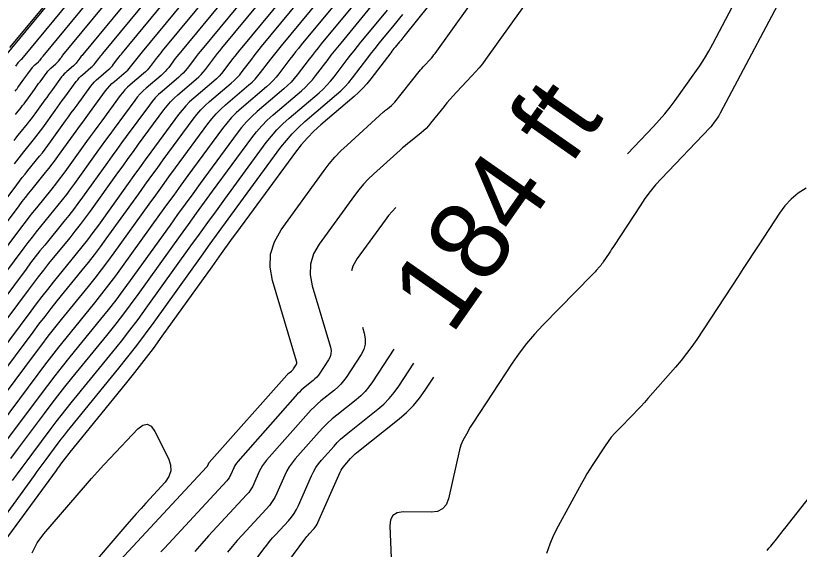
# Model space of a CAD drawing. Extents: x 7585033 to 7595090, y 547091 to 553471.
# Drawn here: x 7587044.7 to 7587106.7, y 548097.5 to 548139.7 of the extents above; entities that cross this region are included whole.
import ezdxf

# ---------------------------------------------------------------- set-up
doc = ezdxf.new("R2010")
doc.units = 0
for name, color, linetype in [('E_TERR_DSPLAY_GeneralTx', 7, 'Continuous'), ('E_TERR_DSPLAY_MajContour', 7, 'Continuous'), ('E_TERR_DSPLAY_MinContour', 7, 'Continuous')]:
    doc.layers.add(name, color=color, linetype=linetype)

msp = doc.modelspace()

# ---------------------------------------------------------------- linework, layer by layer
at = {"layer": 'E_TERR_DSPLAY_MajContour'}
for points in [[(7587067.906, 548163.768), (7587045.286, 548136.421), (7587045.27, 548136.402), (7587045.255, 548136.383), (7587045.24, 548136.363), (7587045.224, 548136.343), (7587045.164, 548136.264), (7587045.148, 548136.245), (7587045.132, 548136.226), (7587045.114, 548136.209), (7587045.096, 548136.192), (7587044.959, 548136.076), (7587044.931, 548136.05), (7587044.904, 548136.023), (7587044.879, 548135.995), (7587044.856, 548135.965), (7587044.668, 548135.708)], [(7587044.586, 548127.968), (7587044.768, 548128.209), (7587044.952, 548128.449), (7587045.139, 548128.686), (7587045.329, 548128.921), (7587046.093, 548129.858), (7587046.282, 548130.094), (7587046.467, 548130.333), (7587046.649, 548130.574), (7587046.827, 548130.818), (7587047.819, 548132.198), (7587048.005, 548132.457), (7587048.193, 548132.716), (7587048.381, 548132.974), (7587048.57, 548133.232), (7587049.485, 548134.478), (7587049.599, 548134.624), (7587049.721, 548134.763), (7587049.85, 548134.894), (7587049.988, 548135.018), (7587050.651, 548135.582), (7587050.741, 548135.663), (7587050.826, 548135.748), (7587050.906, 548135.837), (7587050.982, 548135.932), (7587051.275, 548136.317), (7587051.349, 548136.413), (7587051.424, 548136.508), (7587051.5, 548136.603), (7587051.576, 548136.696), (7587068.498, 548157.153)], [(7587069.089, 548150.539), (7587057.866, 548136.971), (7587057.729, 548136.803), (7587057.593, 548136.634), (7587057.459, 548136.463), (7587057.326, 548136.291), (7587056.8, 548135.599), (7587056.665, 548135.43), (7587056.52, 548135.27), (7587056.368, 548135.117), (7587056.206, 548134.972), (7587055.016, 548133.96), (7587054.769, 548133.738), (7587054.537, 548133.502), (7587054.319, 548133.254), (7587054.115, 548132.992), (7587052.472, 548130.755), (7587052.133, 548130.293), (7587051.796, 548129.829), (7587051.459, 548129.365), (7587051.124, 548128.9), (7587049.345, 548126.424), (7587049.026, 548125.986), (7587048.699, 548125.553), (7587048.367, 548125.125), (7587048.027, 548124.702), (7587046.657, 548123.021), (7587046.317, 548122.599), (7587045.981, 548122.173), (7587045.65, 548121.744), (7587045.324, 548121.311), (7587032.978, 548104.768)], [(7587038.984, 548105.17), (7587046.061, 548114.653), (7587046.532, 548115.278), (7587047.01, 548115.897), (7587047.495, 548116.511), (7587047.985, 548117.12), (7587049.962, 548119.547), (7587050.451, 548120.157), (7587050.931, 548120.774), (7587051.402, 548121.399), (7587051.863, 548122.03), (7587054.429, 548125.602), (7587054.913, 548126.273), (7587055.398, 548126.943), (7587055.885, 548127.612), (7587056.374, 548128.279), (7587058.744, 548131.506), (7587059.038, 548131.883), (7587059.353, 548132.242), (7587059.688, 548132.581), (7587060.044, 548132.902), (7587061.761, 548134.362), (7587061.994, 548134.571), (7587062.214, 548134.791), (7587062.423, 548135.023), (7587062.618, 548135.267), (7587063.378, 548136.264), (7587063.569, 548136.513), (7587063.762, 548136.759), (7587063.958, 548137.004), (7587064.157, 548137.246), (7587070.413, 548144.811)], [(7587044.307, 548104.655), (7587044.837, 548105.367), (7587046.96, 548108.212), (7587047.495, 548108.921), (7587048.037, 548109.623), (7587048.586, 548110.32), (7587049.143, 548111.011), (7587051.897, 548114.391), (7587052.536, 548115.188), (7587053.164, 548115.995), (7587053.779, 548116.811), (7587054.381, 548117.636), (7587057.735, 548122.304), (7587058.367, 548123.181), (7587059.001, 548124.056), (7587059.638, 548124.93), (7587060.277, 548125.802), (7587063.373, 548130.019), (7587063.758, 548130.512), (7587064.17, 548130.981), (7587064.608, 548131.425), (7587065.072, 548131.844), (7587067.317, 548133.752), (7587067.621, 548134.025), (7587067.909, 548134.313), (7587068.181, 548134.616), (7587068.437, 548134.935), (7587069.429, 548136.238), (7587069.678, 548136.563), (7587069.931, 548136.885), (7587070.187, 548137.204), (7587070.447, 548137.521), (7587073.08, 548140.705)], [(7587107.269, 548126.052), (7587106.649, 548125.651), (7587106.09, 548125.186), (7587105.592, 548124.657), (7587105.153, 548124.063), (7587103.52, 548121.561), (7587103.111, 548120.936), (7587102.702, 548120.311), (7587102.292, 548119.687), (7587101.882, 548119.063), (7587098.603, 548114.082), (7587098.213, 548113.511), (7587097.803, 548112.955), (7587097.375, 548112.413), (7587096.927, 548111.886), (7587094.741, 548109.402), (7587094.46, 548109.086), (7587094.174, 548108.775), (7587093.884, 548108.468), (7587093.59, 548108.165), (7587092.405, 548106.961), (7587092.117, 548106.653), (7587091.845, 548106.332), (7587091.589, 548105.998), (7587091.35, 548105.651), (7587090.379, 548104.17), (7587090.144, 548103.803), (7587089.916, 548103.431), (7587089.696, 548103.056), (7587089.482, 548102.675), (7587087.63, 548099.294), (7587087.277, 548098.593), (7587086.976, 548097.873), (7587086.726, 548097.133)], [(7587074.625, 548113.305), (7587072.937, 548110.729), (7587072.656, 548110.334), (7587072.346, 548109.966), (7587072.008, 548109.624), (7587071.641, 548109.307), (7587070.117, 548108.095), (7587069.743, 548107.784), (7587069.383, 548107.458), (7587069.038, 548107.116), (7587068.708, 548106.76), (7587066.808, 548104.617), (7587066.565, 548104.32), (7587066.346, 548104.007), (7587066.153, 548103.678), (7587065.985, 548103.333), (7587065.364, 548101.921), (7587065.196, 548101.576), (7587065, 548101.25), (7587064.778, 548100.94), (7587064.529, 548100.649), (7587062.621, 548098.595), (7587062.222, 548098.153), (7587061.835, 548097.7), (7587061.462, 548097.237)], [(7587045.995, 548097.192), (7587046.384, 548097.97), (7587046.914, 548098.693), (7587050.212, 548102.518), (7587050.691, 548103.066), (7587051.176, 548103.609), (7587051.668, 548104.146), (7587052.165, 548104.677), (7587054.36, 548106.991), (7587054.748, 548107.299), (7587055.101, 548107.369), (7587055.418, 548107.2), (7587055.701, 548106.793), (7587056.779, 548104.646), (7587056.954, 548104.15), (7587056.969, 548103.676), (7587056.826, 548103.224), (7587056.523, 548102.794), (7587054.993, 548101.118), (7587054.612, 548100.698), (7587054.235, 548100.275), (7587053.86, 548099.848), (7587053.49, 548099.419), (7587046.587, 548091.362)], [(7587104.186, 548097.382), (7587104.328, 548097.552), (7587104.468, 548097.723), (7587105.021, 548098.413), (7587105.159, 548098.585), (7587105.297, 548098.758), (7587105.434, 548098.931), (7587105.571, 548099.105), (7587110.461, 548105.321)]]:
    msp.add_lwpolyline(points, dxfattribs=at)
at = {"layer": 'E_TERR_DSPLAY_MinContour'}
for points in [[(7587044.642, 548133.725), (7587044.718, 548133.821), (7587044.793, 548133.917), (7587044.867, 548134.015), (7587044.939, 548134.113), (7587045.339, 548134.671), (7587045.415, 548134.776), (7587045.491, 548134.881), (7587045.567, 548134.985), (7587045.643, 548135.089), (7587046.013, 548135.593), (7587046.059, 548135.652), (7587046.109, 548135.708), (7587046.161, 548135.761), (7587046.216, 548135.811), (7587046.485, 548136.039), (7587046.521, 548136.072), (7587046.555, 548136.107), (7587046.588, 548136.143), (7587046.619, 548136.181), (7587046.737, 548136.337), (7587046.767, 548136.375), (7587046.797, 548136.414), (7587046.828, 548136.452), (7587046.859, 548136.49), (7587068.054, 548162.114)], [(7587044.665, 548131.871), (7587045.125, 548132.436), (7587045.239, 548132.578), (7587045.351, 548132.722), (7587045.461, 548132.868), (7587045.568, 548133.015), (7587046.166, 548133.847), (7587046.278, 548134.003), (7587046.391, 548134.159), (7587046.505, 548134.315), (7587046.619, 548134.47), (7587047.171, 548135.222), (7587047.239, 548135.31), (7587047.313, 548135.393), (7587047.391, 548135.472), (7587047.473, 548135.547), (7587047.873, 548135.887), (7587047.928, 548135.936), (7587047.979, 548135.987), (7587048.027, 548136.041), (7587048.073, 548136.098), (7587048.25, 548136.33), (7587048.294, 548136.388), (7587048.339, 548136.445), (7587048.385, 548136.502), (7587048.431, 548136.559), (7587068.202, 548160.461)], [(7587068.35, 548158.807), (7587050.004, 548136.627), (7587049.942, 548136.552), (7587049.882, 548136.477), (7587049.822, 548136.4), (7587049.763, 548136.324), (7587049.528, 548136.015), (7587049.467, 548135.939), (7587049.403, 548135.867), (7587049.334, 548135.799), (7587049.262, 548135.735), (7587048.731, 548135.282), (7587048.62, 548135.183), (7587048.517, 548135.078), (7587048.419, 548134.967), (7587048.328, 548134.85), (7587047.594, 548133.851), (7587047.443, 548133.644), (7587047.292, 548133.437), (7587047.142, 548133.23), (7587046.992, 548133.022), (7587046.198, 548131.916), (7587046.055, 548131.721), (7587045.909, 548131.527), (7587045.761, 548131.336), (7587045.609, 548131.147), (7587044.997, 548130.396), (7587044.845, 548130.208), (7587044.695, 548130.017), (7587044.547, 548129.826)], [(7587052.936, 548096.584), (7587059.831, 548104.007), (7587059.851, 548104.031), (7587059.869, 548104.056), (7587059.885, 548104.082), (7587059.898, 548104.109), (7587059.948, 548104.223), (7587059.961, 548104.25), (7587059.977, 548104.277), (7587059.994, 548104.302), (7587060.014, 548104.326), (7587066.163, 548111.26), (7587066.204, 548111.303), (7587066.246, 548111.345), (7587066.29, 548111.385), (7587066.336, 548111.423), (7587066.522, 548111.572), (7587066.567, 548111.611), (7587066.609, 548111.652), (7587066.647, 548111.698), (7587066.681, 548111.746), (7587066.886, 548112.058), (7587066.922, 548112.128), (7587066.942, 548112.201), (7587066.944, 548112.276), (7587066.929, 548112.353), (7587065.025, 548118.732), (7587064.823, 548119.8), (7587064.871, 548120.826), (7587065.166, 548121.81), (7587065.709, 548122.752), (7587069.105, 548127.434), (7587069.519, 548127.975), (7587069.96, 548128.493), (7587070.428, 548128.987), (7587070.921, 548129.457), (7587073.815, 548132.073), (7587073.89, 548132.139), (7587073.965, 548132.204), (7587074.042, 548132.268), (7587074.119, 548132.331), (7587074.43, 548132.58), (7587074.506, 548132.645), (7587074.578, 548132.713), (7587074.646, 548132.785), (7587074.71, 548132.861), (7587076.636, 548135.28), (7587076.737, 548135.403), (7587076.84, 548135.524), (7587076.946, 548135.643), (7587077.055, 548135.76), (7587077.494, 548136.222), (7587077.602, 548136.339), (7587077.705, 548136.46), (7587077.804, 548136.584), (7587077.899, 548136.712), (7587093.628, 548158.682)], [(7587091.007, 548157.464), (7587075.431, 548138.056), (7587075.344, 548137.948), (7587075.256, 548137.84), (7587075.168, 548137.733), (7587075.08, 548137.626), (7587074.727, 548137.199), (7587074.639, 548137.092), (7587074.552, 548136.983), (7587074.467, 548136.874), (7587074.382, 548136.765), (7587072.8, 548134.685), (7587072.499, 548134.311), (7587072.179, 548133.954), (7587071.841, 548133.616), (7587071.483, 548133.295), (7587068.843, 548131.05), (7587068.297, 548130.557), (7587067.782, 548130.036), (7587067.298, 548129.484), (7587066.845, 548128.904), (7587063.203, 548123.945), (7587062.452, 548122.919), (7587061.703, 548121.892), (7587060.957, 548120.862), (7587060.214, 548119.83), (7587056.27, 548114.341), (7587055.561, 548113.37), (7587054.838, 548112.41), (7587054.1, 548111.461), (7587053.348, 548110.524), (7587048.983, 548105.166), (7587048.887, 548105.048), (7587048.793, 548104.928), (7587048.7, 548104.808), (7587048.609, 548104.687), (7587048.245, 548104.199), (7587048.154, 548104.077), (7587048.064, 548103.955), (7587047.973, 548103.832), (7587047.884, 548103.709), (7587043.829, 548098.153)], [(7587060.166, 548156.242), (7587043.714, 548136.352)], [(7587044.234, 548137.172), (7587060.142, 548156.262)], [(7587028.473, 548104.467), (7587044.77, 548126.304), (7587044.988, 548126.593), (7587045.21, 548126.88), (7587045.434, 548127.164), (7587045.661, 548127.446), (7587046.576, 548128.569), (7587046.803, 548128.852), (7587047.025, 548129.138), (7587047.243, 548129.427), (7587047.457, 548129.719), (7587048.645, 548131.373), (7587048.869, 548131.684), (7587049.094, 548131.994), (7587049.319, 548132.304), (7587049.545, 548132.613), (7587050.643, 548134.107), (7587050.779, 548134.282), (7587050.925, 548134.448), (7587051.08, 548134.605), (7587051.245, 548134.753), (7587052.04, 548135.43), (7587052.148, 548135.526), (7587052.25, 548135.628), (7587052.346, 548135.736), (7587052.437, 548135.848), (7587052.788, 548136.31), (7587052.877, 548136.425), (7587052.966, 548136.54), (7587053.057, 548136.653), (7587053.149, 548136.765), (7587068.646, 548155.5)], [(7587029.975, 548104.567), (7587044.955, 548124.639), (7587045.209, 548124.976), (7587045.467, 548125.311), (7587045.728, 548125.642), (7587045.993, 548125.971), (7587047.06, 548127.28), (7587047.324, 548127.61), (7587047.583, 548127.943), (7587047.837, 548128.28), (7587048.086, 548128.621), (7587049.471, 548130.549), (7587049.732, 548130.911), (7587049.994, 548131.273), (7587050.257, 548131.633), (7587050.521, 548131.994), (7587051.8, 548133.735), (7587051.959, 548133.939), (7587052.129, 548134.133), (7587052.31, 548134.316), (7587052.502, 548134.489), (7587053.429, 548135.277), (7587053.554, 548135.39), (7587053.673, 548135.509), (7587053.785, 548135.634), (7587053.891, 548135.765), (7587054.301, 548136.304), (7587054.404, 548136.438), (7587054.508, 548136.571), (7587054.614, 548136.703), (7587054.721, 548136.834), (7587068.793, 548153.846)], [(7587094.383, 548153.685), (7587081.886, 548136.23), (7587081.635, 548135.891), (7587081.372, 548135.561), (7587081.097, 548135.241), (7587080.812, 548134.93), (7587079.58, 548133.635), (7587079.326, 548133.361), (7587079.077, 548133.082), (7587078.835, 548132.798), (7587078.6, 548132.509), (7587077.54, 548131.178), (7587077.366, 548130.972), (7587077.182, 548130.777), (7587076.987, 548130.592), (7587076.782, 548130.418), (7587075.939, 548129.744), (7587075.73, 548129.573), (7587075.523, 548129.4), (7587075.319, 548129.224), (7587075.117, 548129.044), (7587073.013, 548127.143), (7587072.607, 548126.755), (7587072.222, 548126.349), (7587071.859, 548125.923), (7587071.518, 548125.477), (7587068.722, 548121.622), (7587068.274, 548120.847), (7587068.031, 548120.037), (7587067.992, 548119.192), (7587068.158, 548118.312), (7587069.605, 548113.464), (7587069.656, 548113.202), (7587069.649, 548112.948), (7587069.583, 548112.702), (7587069.46, 548112.465), (7587068.767, 548111.407), (7587068.65, 548111.243), (7587068.521, 548111.09), (7587068.381, 548110.948), (7587068.229, 548110.817), (7587067.596, 548110.314), (7587067.441, 548110.185), (7587067.292, 548110.049), (7587067.149, 548109.908), (7587067.011, 548109.76), (7587062.279, 548104.423), (7587062.184, 548104.308), (7587062.1, 548104.187), (7587062.025, 548104.06), (7587061.96, 548103.926), (7587061.72, 548103.38), (7587061.655, 548103.247), (7587061.579, 548103.12), (7587061.493, 548103.001), (7587061.397, 548102.888), (7587056.459, 548097.572), (7587056.175, 548097.256)], [(7587068.941, 548152.193), (7587056.294, 548136.902), (7587056.172, 548136.753), (7587056.051, 548136.602), (7587055.931, 548136.45), (7587055.814, 548136.297), (7587055.346, 548135.682), (7587055.225, 548135.532), (7587055.097, 548135.389), (7587054.961, 548135.253), (7587054.817, 548135.125), (7587053.759, 548134.224), (7587053.54, 548134.027), (7587053.333, 548133.817), (7587053.139, 548133.596), (7587052.957, 548133.364), (7587051.497, 548131.375), (7587051.195, 548130.963), (7587050.895, 548130.551), (7587050.596, 548130.138), (7587050.298, 548129.724), (7587048.716, 548127.523), (7587048.431, 548127.133), (7587048.141, 548126.748), (7587047.845, 548126.368), (7587047.544, 548125.991), (7587046.325, 548124.496), (7587046.023, 548124.12), (7587045.724, 548123.742), (7587045.43, 548123.36), (7587045.139, 548122.975), (7587031.476, 548104.668)], [(7587069.237, 548148.885), (7587059.439, 548137.04), (7587059.286, 548136.853), (7587059.135, 548136.665), (7587058.986, 548136.475), (7587058.839, 548136.284), (7587058.255, 548135.516), (7587058.104, 548135.329), (7587057.944, 548135.15), (7587057.774, 548134.98), (7587057.595, 548134.82), (7587056.273, 548133.695), (7587055.999, 548133.448), (7587055.741, 548133.187), (7587055.499, 548132.911), (7587055.272, 548132.62), (7587053.448, 548130.136), (7587053.071, 548129.622), (7587052.696, 548129.108), (7587052.323, 548128.592), (7587051.95, 548128.075), (7587049.975, 548125.326), (7587049.62, 548124.839), (7587049.257, 548124.359), (7587048.888, 548123.883), (7587048.511, 548123.414), (7587046.989, 548121.546), (7587046.611, 548121.077), (7587046.239, 548120.604), (7587045.871, 548120.127), (7587045.508, 548119.646), (7587034.479, 548104.869)], [(7587035.981, 548104.969), (7587045.692, 548117.982), (7587046.091, 548118.511), (7587046.496, 548119.035), (7587046.906, 548119.555), (7587047.321, 548120.071), (7587048.995, 548122.125), (7587049.409, 548122.641), (7587049.815, 548123.164), (7587050.214, 548123.692), (7587050.604, 548124.227), (7587052.777, 548127.251), (7587053.186, 548127.819), (7587053.597, 548128.386), (7587054.009, 548128.952), (7587054.423, 548129.517), (7587056.429, 548132.249), (7587056.679, 548132.568), (7587056.945, 548132.872), (7587057.229, 548133.159), (7587057.53, 548133.431), (7587058.984, 548134.667), (7587059.181, 548134.844), (7587059.367, 548135.03), (7587059.544, 548135.227), (7587059.709, 548135.433), (7587060.352, 548136.278), (7587060.514, 548136.488), (7587060.678, 548136.697), (7587060.843, 548136.903), (7587061.011, 548137.109), (7587069.385, 548147.232)], [(7587069.747, 548145.837), (7587062.584, 548137.177), (7587062.401, 548136.954), (7587062.22, 548136.728), (7587062.041, 548136.5), (7587061.865, 548136.271), (7587061.164, 548135.35), (7587060.983, 548135.125), (7587060.791, 548134.911), (7587060.587, 548134.707), (7587060.373, 548134.515), (7587058.787, 548133.166), (7587058.459, 548132.87), (7587058.149, 548132.557), (7587057.858, 548132.226), (7587057.587, 548131.877), (7587055.399, 548128.898), (7587054.947, 548128.282), (7587054.498, 548127.664), (7587054.05, 548127.046), (7587053.603, 548126.426), (7587051.234, 548123.129), (7587050.808, 548122.545), (7587050.373, 548121.969), (7587049.93, 548121.399), (7587049.478, 548120.836), (7587047.653, 548118.596), (7587047.2, 548118.033), (7587046.753, 548117.466), (7587046.312, 548116.894), (7587045.877, 548116.318), (7587037.483, 548105.07)], [(7587093.124, 548128.754), (7587095.19, 548130.926), (7587095.644, 548131.421), (7587096.08, 548131.93), (7587096.499, 548132.455), (7587096.899, 548132.994), (7587098.465, 548135.182), (7587098.847, 548135.734), (7587099.21, 548136.299), (7587099.553, 548136.876), (7587099.877, 548137.464), (7587104.275, 548145.787)], [(7587040.486, 548105.271), (7587046.246, 548112.989), (7587046.753, 548113.661), (7587047.267, 548114.328), (7587047.789, 548114.99), (7587048.317, 548115.645), (7587050.446, 548118.258), (7587050.973, 548118.915), (7587051.489, 548119.579), (7587051.996, 548120.252), (7587052.493, 548120.932), (7587055.256, 548124.777), (7587055.777, 548125.5), (7587056.299, 548126.221), (7587056.824, 548126.941), (7587057.35, 548127.66), (7587059.901, 548131.134), (7587060.218, 548131.54), (7587060.557, 548131.926), (7587060.918, 548132.292), (7587061.301, 548132.637), (7587063.15, 548134.21), (7587063.401, 548134.434), (7587063.638, 548134.672), (7587063.862, 548134.922), (7587064.073, 548135.184), (7587064.89, 548136.258), (7587065.096, 548136.525), (7587065.304, 548136.791), (7587065.515, 548137.054), (7587065.729, 548137.315), (7587071.08, 548143.784)], [(7587106.336, 548143.087), (7587100.465, 548131.979), (7587100.408, 548131.875), (7587100.347, 548131.772), (7587100.282, 548131.672), (7587100.214, 548131.573), (7587099.936, 548131.185), (7587099.865, 548131.089), (7587099.791, 548130.996), (7587099.713, 548130.905), (7587099.632, 548130.817), (7587095.814, 548126.802), (7587095.354, 548126.295), (7587094.917, 548125.769), (7587094.505, 548125.223), (7587094.118, 548124.658), (7587092.061, 548121.507), (7587091.964, 548121.358), (7587091.866, 548121.21), (7587091.769, 548121.061), (7587091.671, 548120.912), (7587091.206, 548120.207), (7587091.144, 548120.115), (7587091.078, 548120.025), (7587091.009, 548119.938), (7587090.937, 548119.853), (7587090.642, 548119.518), (7587090.568, 548119.435), (7587090.493, 548119.353), (7587090.416, 548119.272), (7587090.338, 548119.192), (7587086.415, 548115.205), (7587085.754, 548114.499), (7587085.13, 548113.763), (7587084.543, 548112.997), (7587083.993, 548112.201), (7587080.888, 548107.46), (7587080.781, 548107.292), (7587080.676, 548107.122), (7587080.575, 548106.95), (7587080.478, 548106.776), (7587080.094, 548106.076), (7587080.005, 548105.898), (7587079.928, 548105.716), (7587079.865, 548105.528), (7587079.815, 548105.336), (7587078.948, 548101.474), (7587078.772, 548101), (7587078.488, 548100.663), (7587078.095, 548100.463), (7587077.593, 548100.401), (7587075.369, 548100.425), (7587074.886, 548100.36), (7587074.548, 548100.156), (7587074.354, 548099.811), (7587074.306, 548099.326), (7587074.446, 548096.147)], [(7587071.747, 548142.758), (7587067.302, 548137.384), (7587067.073, 548137.104), (7587066.847, 548136.822), (7587066.623, 548136.538), (7587066.403, 548136.251), (7587065.528, 548135.101), (7587065.302, 548134.82), (7587065.062, 548134.552), (7587064.807, 548134.298), (7587064.539, 548134.057), (7587062.558, 548132.373), (7587062.148, 548132.003), (7587061.761, 548131.611), (7587061.398, 548131.198), (7587061.059, 548130.762), (7587058.325, 548127.041), (7587057.762, 548126.271), (7587057.2, 548125.5), (7587056.64, 548124.727), (7587056.082, 548123.953), (7587053.122, 548119.833), (7587052.59, 548119.105), (7587052.047, 548118.384), (7587051.494, 548117.672), (7587050.929, 548116.969), (7587048.649, 548114.17), (7587048.083, 548113.468), (7587047.525, 548112.759), (7587046.974, 548112.045), (7587046.43, 548111.325), (7587041.987, 548105.371)], [(7587072.414, 548141.731), (7587068.874, 548137.452), (7587068.63, 548137.154), (7587068.389, 548136.854), (7587068.151, 548136.55), (7587067.916, 548136.245), (7587066.982, 548135.018), (7587066.741, 548134.718), (7587066.485, 548134.433), (7587066.214, 548134.161), (7587065.928, 548133.905), (7587063.815, 548132.108), (7587063.378, 548131.714), (7587062.965, 548131.296), (7587062.578, 548130.855), (7587062.216, 548130.391), (7587059.301, 548126.422), (7587058.7, 548125.601), (7587058.1, 548124.778), (7587057.503, 548123.954), (7587056.909, 548123.128), (7587053.752, 548118.735), (7587053.184, 548117.958), (7587052.606, 548117.19), (7587052.015, 548116.43), (7587051.413, 548115.68), (7587048.982, 548112.695), (7587048.378, 548111.946), (7587047.782, 548111.19), (7587047.194, 548110.429), (7587046.615, 548109.66), (7587043.489, 548105.472)], [(7587044.447, 548102.91), (7587044.826, 548103.428), (7587045.207, 548103.946), (7587045.589, 548104.462), (7587045.973, 548104.977), (7587047.51, 548107.037), (7587047.897, 548107.55), (7587048.289, 548108.058), (7587048.687, 548108.563), (7587049.09, 548109.063), (7587052.38, 548113.102), (7587053.057, 548113.946), (7587053.722, 548114.8), (7587054.373, 548115.664), (7587055.011, 548116.538), (7587058.561, 548121.479), (7587059.23, 548122.408), (7587059.902, 548123.335), (7587060.576, 548124.26), (7587061.252, 548125.183), (7587064.531, 548129.647), (7587064.938, 548130.17), (7587065.374, 548130.666), (7587065.837, 548131.136), (7587066.329, 548131.579), (7587068.705, 548133.6), (7587069.027, 548133.889), (7587069.332, 548134.193), (7587069.62, 548134.514), (7587069.891, 548134.851), (7587070.941, 548136.232), (7587071.206, 548136.575), (7587071.473, 548136.916), (7587071.745, 548137.254), (7587072.019, 548137.59), (7587073.747, 548139.679), (7587074.126, 548140.139)], [(7587042.613, 548098.442), (7587046.165, 548103.31), (7587046.4, 548103.63), (7587046.635, 548103.95), (7587046.872, 548104.269), (7587047.109, 548104.588), (7587048.059, 548105.862), (7587048.299, 548106.179), (7587048.541, 548106.493), (7587048.787, 548106.805), (7587049.036, 548107.115), (7587052.864, 548111.813), (7587053.579, 548112.704), (7587054.28, 548113.605), (7587054.967, 548114.517), (7587055.64, 548115.44), (7587059.388, 548120.655), (7587060.094, 548121.635), (7587060.803, 548122.613), (7587061.514, 548123.59), (7587062.228, 548124.564), (7587065.688, 548129.276), (7587066.118, 548129.827), (7587066.578, 548130.351), (7587067.067, 548130.847), (7587067.586, 548131.315), (7587070.094, 548133.447), (7587070.434, 548133.752), (7587070.756, 548134.074), (7587071.06, 548134.413), (7587071.346, 548134.768), (7587072.563, 548136.369), (7587072.787, 548136.66), (7587073.014, 548136.949), (7587073.244, 548137.235), (7587073.477, 548137.52), (7587074.414, 548138.652), (7587074.647, 548138.936), (7587074.88, 548139.22), (7587075.112, 548139.506), (7587075.342, 548139.792)], [(7587074.784, 548124.523), (7587074.483, 548124.205), (7587074.198, 548123.87), (7587073.93, 548123.52), (7587071.734, 548120.492), (7587071.383, 548119.883), (7587071.267, 548119.496)], [(7587072.143, 548115.042), (7587072.282, 548114.575), (7587072.368, 548114.128), (7587072.356, 548113.695), (7587072.244, 548113.276), (7587072.034, 548112.872), (7587070.852, 548111.068), (7587070.653, 548110.789), (7587070.434, 548110.528), (7587070.194, 548110.286), (7587069.935, 548110.062), (7587068.856, 548109.204), (7587068.592, 548108.984), (7587068.338, 548108.754), (7587068.094, 548108.512), (7587067.86, 548108.26), (7587064.543, 548104.52), (7587064.375, 548104.314), (7587064.223, 548104.097), (7587064.089, 548103.869), (7587063.973, 548103.63), (7587063.542, 548102.65), (7587063.425, 548102.411), (7587063.29, 548102.185), (7587063.136, 548101.971), (7587062.963, 548101.768), (7587059.966, 548098.542), (7587059.414, 548097.931), (7587058.88, 548097.306)], [(7587057.522, 548088.307), (7587064.336, 548097.515), (7587064.559, 548097.808), (7587064.79, 548098.095), (7587065.029, 548098.375), (7587065.276, 548098.648), (7587066.279, 548099.728), (7587066.517, 548100.006), (7587066.729, 548100.302), (7587066.916, 548100.614), (7587067.077, 548100.943), (7587068.102, 548103.274), (7587068.265, 548103.609), (7587068.453, 548103.929), (7587068.665, 548104.232), (7587068.901, 548104.52), (7587069.895, 548105.641), (7587070.149, 548105.915), (7587070.414, 548106.178), (7587070.69, 548106.429), (7587070.978, 548106.668), (7587073.347, 548108.553), (7587073.822, 548108.961), (7587074.259, 548109.404), (7587074.659, 548109.88), (7587075.022, 548110.39), (7587076.207, 548112.198)], [(7587058.156, 548085.545), (7587067.571, 548098.267), (7587067.656, 548098.379), (7587067.745, 548098.489), (7587067.836, 548098.596), (7587067.931, 548098.701), (7587068.315, 548099.115), (7587068.406, 548099.222), (7587068.488, 548099.335), (7587068.559, 548099.454), (7587068.621, 548099.58), (7587070.372, 548103.563), (7587070.448, 548103.718), (7587070.534, 548103.866), (7587070.632, 548104.006), (7587070.741, 548104.139), (7587071.2, 548104.656), (7587071.317, 548104.783), (7587071.439, 548104.904), (7587071.567, 548105.02), (7587071.7, 548105.13), (7587075.054, 548107.798), (7587075.635, 548108.299), (7587076.171, 548108.842), (7587076.662, 548109.425), (7587077.108, 548110.05), (7587077.789, 548111.091)]]:
    msp.add_lwpolyline(points, dxfattribs=at)

# ---------------------------------------------------------------- texts
at = {"layer": 'E_TERR_DSPLAY_GeneralTx'}
msp.add_text('184 ft', height=6.3, rotation=55.01573, dxfattribs=at).set_placement((7587079.19, 548114.336))

doc.saveas('drawing.dxf')
